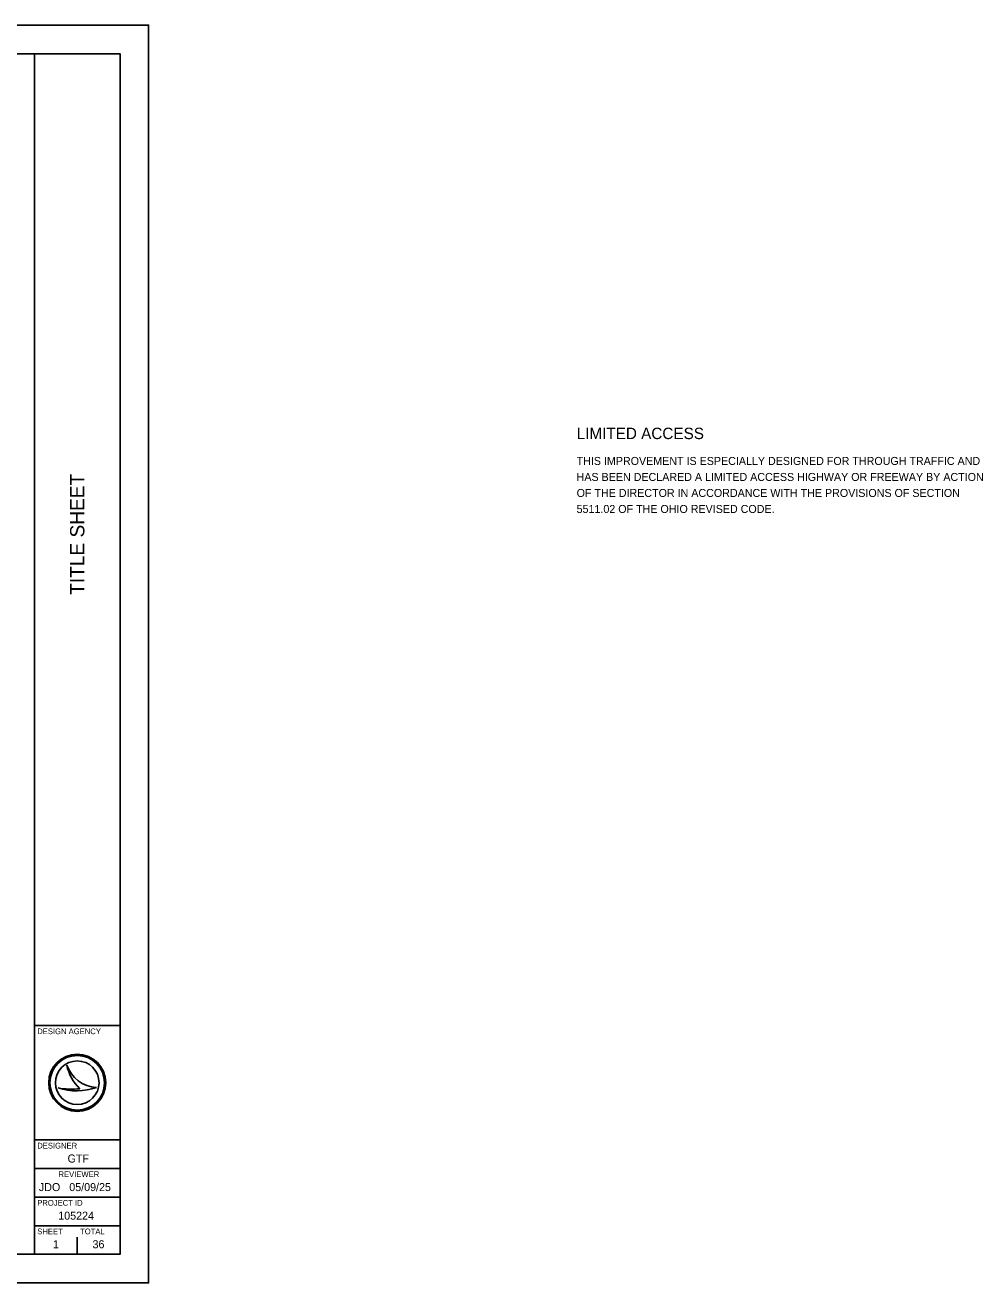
# Model space of a CAD drawing. Extents: x 0 to 48.6, y 0 to 22.
# Drawn here: x 31.84 to 48.6, y 0 to 22 of the extents above; entities that cross this region are included whole.
import ezdxf

# ---------------------------------------------------------------- set-up
doc = ezdxf.new("R2010")
doc.units = 0
for name, color, linetype in [('SH_Border', 7, 'Continuous'), ('SH_Cut_Line', 7, 'Continuous'), ('SH_Data', 7, 'Continuous'), ('SH_Text', 7, 'Continuous')]:
    doc.layers.add(name, color=color, linetype=linetype)

msp = doc.modelspace()

# ---------------------------------------------------------------- linework, layer by layer
at = {"layer": 'SH_Border'}
for p, q in [((32, 0.5), (32, 21.5)), ((32, 4.5), (33.5, 4.5)), ((32, 2.5), (33.5, 2.5)), ((32, 2), (33.5, 2)), ((32, 1.5), (33.5, 1.5)), ((32, 1), (33.5, 1))]:
    msp.add_line(p, q, dxfattribs=at)
msp.add_lwpolyline([(1.5, 21.5), (33.5, 21.5), (33.5, 0.5), (1.5, 0.5)], close=True, dxfattribs=at)
at = {"layer": 'SH_Cut_Line'}
msp.add_lwpolyline([(0, 0), (34, 0), (34, 22), (0, 22)], close=True, dxfattribs=at)
at = {"layer": 'SH_Data'}
for p, q in [((32.567, 3.81), (32.567, 3.81)), ((32.417, 3.41), (32.417, 3.41)), ((32.75, 3.5), (32.75, 3.5)), ((33.087, 3.419), (33.087, 3.419)), ((32.375, 0.675), (32.375, 0.675)), ((32.75, 0.5), (32.75, 0.8))]:
    msp.add_line(p, q, dxfattribs=at)
for radius in [0.5, 0.477, 0.477, 0.382]:
    msp.add_circle((32.75, 3.5), radius, dxfattribs=at)
for centre, radius, start, end in [((33.116, 3.998), 0.58, 198.9257, 198.9319), ((33.347, 3.97), 0.796, 191.6379, 191.6421), ((33.116, 3.998), 0.58, 198.9319, 267.1657), ((33.347, 3.97), 0.796, 191.6421, 226.0947), ((32.739, 4.37), 1.013, 251.4576, 290.0832), ((32.648, 4.654), 1.266, 259.4964, 259.4995), ((32.739, 4.37), 1.013, 251.4527, 251.4576), ((32.648, 4.654), 1.266, 259.4995, 276.6672)]:
    msp.add_arc(centre, radius, start, end, dxfattribs=at)

# ---------------------------------------------------------------- texts
msp.add_text('TITLE SHEET', height=0.25, rotation=90, dxfattribs=at).set_placement((32.875, 12.035))
for s, height, p in [('DESIGN AGENCY', 0.1, (32.05, 4.35)), ('DESIGNER', 0.1, (32.05, 2.35)), ('GTF', 0.14, (32.581, 2.105)), ('REVIEWER', 0.1, (32.422, 1.85)), ('JDO', 0.14, (32.079, 1.605)), ('05/09/25', 0.14, (32.611, 1.605)), ('PROJECT ID', 0.1, (32.05, 1.35)), ('105224', 0.14, (32.418, 1.105)), ('SHEET', 0.1, (32.05, 0.85)), ('TOTAL', 0.1, (32.8, 0.85)), ('1', 0.14, (32.325, 0.605)), ('36', 0.14, (33.018, 0.605))]:
    msp.add_text(s, height=height, dxfattribs=at).set_placement(p)
at = {"layer": 'SH_Text'}
for s, height, p in [('LIMITED ACCESS', 0.2, (41.491, 14.759)), ('THIS IMPROVEMENT IS ESPECIALLY DESIGNED FOR THROUGH TRAFFIC AND', 0.14, (41.491, 14.307)), ('HAS BEEN DECLARED A LIMITED ACCESS HIGHWAY OR FREEWAY BY ACTION', 0.14, (41.491, 14.027)), ('OF THE DIRECTOR IN ACCORDANCE WITH THE PROVISIONS OF SECTION', 0.14, (41.491, 13.747)), ('5511.02 OF THE OHIO REVISED CODE.', 0.14, (41.491, 13.467))]:
    msp.add_text(s, height=height, dxfattribs=at).set_placement(p)

doc.saveas('drawing.dxf')
